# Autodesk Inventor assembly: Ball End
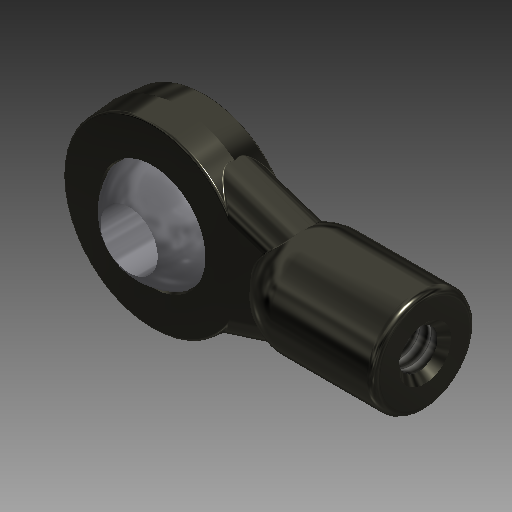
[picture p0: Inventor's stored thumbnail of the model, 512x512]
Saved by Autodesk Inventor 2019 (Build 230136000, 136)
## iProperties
Shininess: 50.0
Compacted: True
Length Units: 11272
Angle Units: 11279
Time Units: 11290
Mass Units: 11286
Length Display Precision: 4
Angle Display Precision: 2
Company: Autodesk
Manager: Lebovitz
Created: 2000-03
Part Number: Ball End
Project: Inventor Samples
User Status: IN PROGRESS
Document SubType Name: Assembly
Designer: The PD Team
Mass: 0.70348 g
Surface Area: 6.19952 cm^2
Volume: 0.425844 cm^3
Density: 1.65196 g/cm^3
Description: asd
Density: 0.0
Volumn: 0.0
Area: 0.0
PropertySet Name: Model Information
Control State: 0
Master: False
Checked Out: False
Checked Out Date: 2018-05-30
Last Check In Date: 2018-05-30
Author: The PD Team
Revision Number: A
Title: Ball End
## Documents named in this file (3)
- C:\Users\itools\Desktop\autodesk_inventor_2018_samples\Models\Assemblies\Suspension\Components\Ball End.iam
- C:\Users\itools\Desktop\autodesk_inventor_2018_samples\Models\Assemblies\Suspension\Components\Ball End.ipt
- C:\Users\itools\Desktop\autodesk_inventor_2018_samples\Models\Assemblies\Suspension\Components\0.25 Ball.ipt
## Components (2 placed, 2 different names)
1. Ball End:1 — Mate:1, Angle:1
2. 0.25 Ball:1 — Mate:1, Angle:1
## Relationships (2: Mate 1, Angle 1)
- Mate:1: Ball End:1 ↔ 0.25 Ball:1
- Angle:1: Ball End:1 ↔ 0.25 Ball:1
